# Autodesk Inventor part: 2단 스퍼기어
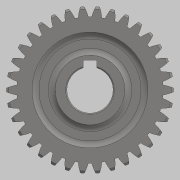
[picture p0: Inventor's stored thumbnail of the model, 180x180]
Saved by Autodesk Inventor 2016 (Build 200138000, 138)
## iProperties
Created: 2018-09
Part Number: 2단 스퍼기어
Material: 스테인레스 스틸
Document SubType Name: Modeling
Designer: MYS
Mass: 384.252 g
Surface Area: 215.76 cm^2
Volume: 48.0315 cm^3
Density: 8 g/cm^3
Appearance: 반연마
Author: MYS
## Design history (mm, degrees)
sketch "스케치1"
  geometry: L1 (0, 0)-(47, 0); L2 (47, 0)-(47, 15); L3 (47, 15)-(0, 15); L4 (0, 15)-(0, 0); L5 (14, 0)-(24, 0); L6 (24, 0)-(24, 36); L7 (24, 36)-(14, 36); L8 (14, 36)-(14, 0); L9 (47, 0)-(37, 0); L10 (37, 0)-(37, 24); L11 (37, 24)-(47, 24); L12 (47, 24)-(47, 0)
  constraints: 24 end point, 6 parallel, 3 horizontal, 3 perpendicular, 1 point on line
  dimensions: "d0" = 47 distance between parallel lines of L2 L4; "d1" = 14 distance between parallel lines of L4 L8; "d2" = 10 distance of L6.end L7.end; "d3" = 10 distance of L10.end L11.end; "d4" = 13 distance between parallel lines of L10 L6 (derived); "d5" = 72 diameter of L7 L1; "d6" = 48 diameter of L11 L1; "d7" = 30 diameter of L3 L1
revolve "회전1" sketch "스케치1" stored, may be unused: angle "d8" = 90 deg
sketch "스케치2"
  geometry: C1 r 25 at (0, 0); C2 r 15 at (0, 0); 1 further point
  constraints: 2 centre point, 2 coincident
  dimensions: "d9" = 50 diameter of C1; "d10" = 30 diameter of C2
extrude "돌출1" cut sketch "스케치2" distance "d11" = 3; taper "d12" = 0 deg
sketch "스케치3"
  geometry: C1 r 25 at (0, 0); C2 r 15 at (0, 0); 1 further point
  constraints: 2 centre point, 2 coincident
  dimensions: "d13" = 50 diameter of C1; "d14" = 30 diameter of C2
extrude "돌출2" cut sketch "스케치3" distance "d15" = 3; taper "d16" = 0 deg
chamfer "모따기2" distance "d35" = 1; stored, may be unused: second distance "d36" = 2, angle "d37" = 45 deg
node "스퍼 기어 톱니1"
node "스퍼 기어 톱니2"
sketch "스케치5"
  geometry: L1 (-3, 12.8)-(3, 12.8); L2 (3, 12.8)-(3, 0); L3 (3, 0)-(-3, 0); L4 (-3, 0)-(-3, 12.8); C1 r 10 at (0, 0); 2 further points
  constraints: 8 end point, 2 coincident, 2 parallel, 1 centre point, 1 horizontal, 1 midpoint, 1 perpendicular
  dimensions: "d38" = 20 diameter of C1; "d39" = 6 distance of L1.start L1.end; "d40" = 22.8 dimension on C1 L1
extrude "돌출4" cut sketch "스케치5" stored distance "d41" = 10; taper "d42" = 0 deg
fillet "모깎기5" dims "d43" = 3
fillet "모깎기6" dims "d44" = 2
chamfer "모따기3" distance "d45" = 0.5; stored, may be unused: second distance "d46" = 2, angle "d47" = 45 deg
node "솔리드1"
feature "스퍼 기어1"
feature "스퍼 기어12"
